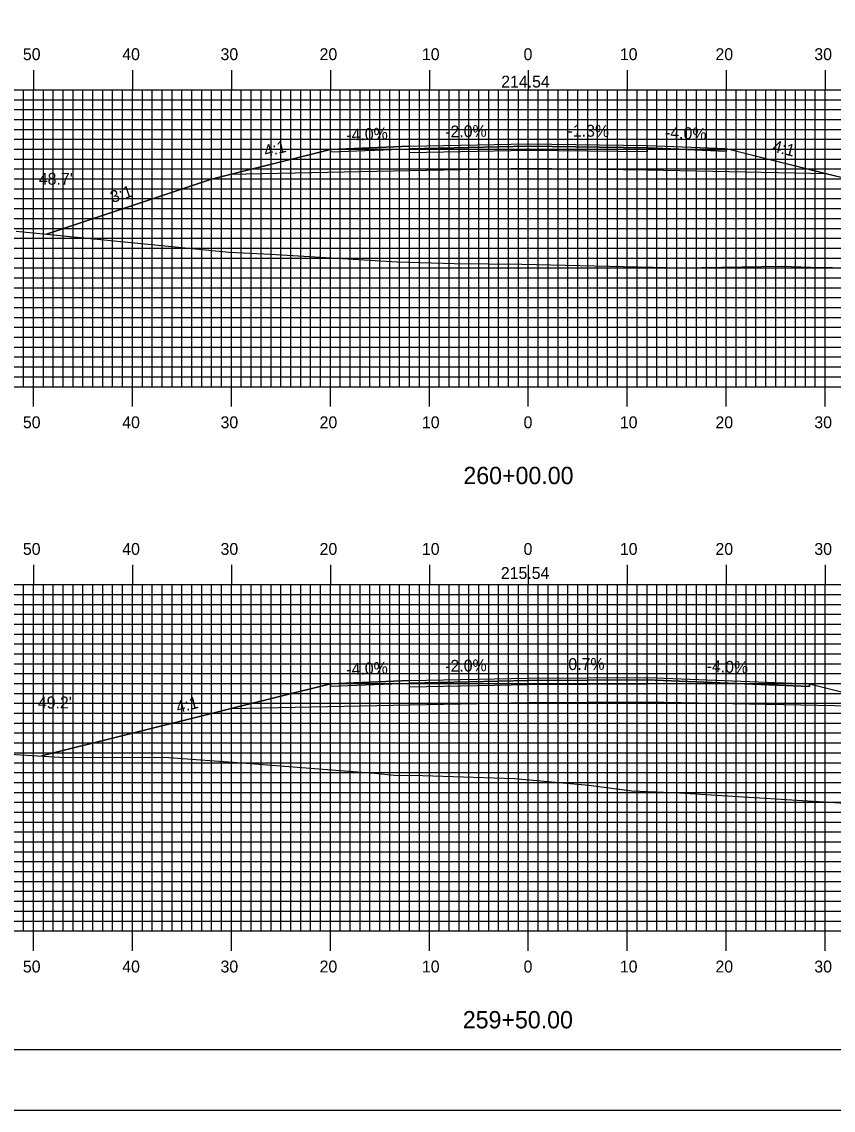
# Model space of a CAD drawing. Extents: x 1805864 to 1806208, y 442591 to 442811.
# Drawn here: x 1805979 to 1806061, y 442590.5 to 442700.5 of the extents above; entities that cross this region are included whole.
import ezdxf

# ---------------------------------------------------------------- set-up
doc = ezdxf.new("R2010")
doc.units = 0
for name, color, linetype in [('ANNOTATION', 7, 'Continuous'), ('BORDER', 7, 'Continuous'), ('D_Roadway_Centerline', 7, 'Continuous'), ('D_Roadway_Centerline_Text', 7, 'Continuous'), ('D_Roadway_Edge_Shoulder', 7, 'Continuous'), ('D_Roadway_Edge_TW', 7, 'Continuous'), ('D_Roadway_Pavement', 7, 'Continuous'), ('D_Roadway_SlopeLines', 7, 'Continuous'), ('D_Roadway_SubGrade', 7, 'Continuous'), ('D_Text_Standard', 7, 'Continuous'), ('H_V ANNOTATION', 7, 'Continuous'), ('MAJOR', 7, 'Continuous'), ('MINOR', 7, 'Continuous'), ('PLOT BOUNDARY', 7, 'Continuous'), ('S_Roadway_Centerline', 7, 'Continuous')]:
    doc.layers.add(name, color=color, linetype=linetype)

msp = doc.modelspace()

# ---------------------------------------------------------------- linework, layer by layer
at = {"layer": 'BORDER'}
msp.add_lwpolyline([(1805880.62, 442596.67), (1806200.62, 442596.67), (1806200.62, 442806.67), (1805880.62, 442806.67)], close=True, dxfattribs=at)
at = {"layer": 'D_Roadway_Centerline'}
for points in [[(1805981.53, 442679.08), (1805998.22, 442684.65), (1806000.05, 442685.1), (1806010.22, 442687.65), (1806018.22, 442687.97), (1806030.22, 442688.21), (1806042.22, 442688.05), (1806050.22, 442687.73), (1806060.39, 442685.19), (1806062.22, 442684.73), (1806093.95, 442674.16)], [(1805981.03, 442626.35), (1805998.22, 442630.65), (1806000.05, 442631.1), (1806010.22, 442633.65), (1806018.22, 442633.97), (1806030.22, 442634.21), (1806042.22, 442634.29), (1806058.63, 442633.63), (1806068.08, 442631.27), (1806070.63, 442630.63), (1806101.56, 442620.32)]]:
    msp.add_lwpolyline(points, dxfattribs=at)
at = {"layer": 'D_Roadway_Edge_Shoulder'}
for points in [[(1806018.22, 442687.97), (1806010.22, 442687.65), (1806010.22, 442687.4), (1806018.22, 442687.72)], [(1806042.22, 442688.05), (1806050.22, 442687.73), (1806050.22, 442687.48), (1806042.22, 442687.8)], [(1806018.22, 442633.97), (1806010.22, 442633.65), (1806010.22, 442633.4), (1806018.22, 442633.72)], [(1806042.22, 442634.29), (1806058.63, 442633.63), (1806058.63, 442633.38), (1806042.22, 442634.04)]]:
    msp.add_lwpolyline(points, close=True, dxfattribs=at)
at = {"layer": 'D_Roadway_Edge_TW'}
for points in [[(1806018.22, 442687.72), (1806018.22, 442687.97), (1806030.22, 442688.21), (1806042.22, 442688.05), (1806042.22, 442687.8), (1806030.22, 442687.96)], [(1806018.22, 442633.72), (1806018.22, 442633.97), (1806030.22, 442634.21), (1806042.22, 442634.29), (1806042.22, 442634.04), (1806030.22, 442633.96)]]:
    msp.add_lwpolyline(points, close=True, dxfattribs=at)
at = {"layer": 'D_Roadway_Pavement'}
for points in [[(1806018.22, 442687.3), (1806018.22, 442687.72), (1806030.22, 442687.96), (1806042.22, 442687.8), (1806042.22, 442687.39), (1806030.22, 442687.54)], [(1806018.22, 442633.3), (1806018.22, 442633.72), (1806030.22, 442633.96), (1806042.22, 442634.04), (1806042.22, 442633.62), (1806030.22, 442633.54)]]:
    msp.add_lwpolyline(points, close=True, dxfattribs=at)
at = {"layer": 'D_Roadway_SlopeLines'}
for points in [[(1806010.22, 442687.65), (1805998.22, 442684.65), (1805981.53, 442679.08)], [(1806050.22, 442687.73), (1806062.22, 442684.73), (1806093.95, 442674.16)], [(1806010.22, 442633.65), (1806000.05, 442631.1), (1805998.22, 442630.65), (1805981.03, 442626.35)], [(1806058.63, 442633.63), (1806070.63, 442630.63), (1806101.56, 442620.32)]]:
    msp.add_lwpolyline(points, dxfattribs=at)
at = {"layer": 'D_Roadway_SubGrade'}
for points in [[(1806018.22, 442685.47), (1806000.05, 442685.1), (1806010.22, 442687.65), (1806010.22, 442687.4), (1806018.22, 442687.72), (1806030.22, 442687.96), (1806042.22, 442687.8), (1806050.22, 442687.48), (1806050.22, 442687.73), (1806060.39, 442685.19), (1806042.22, 442685.55), (1806030.22, 442685.71)], [(1806018.22, 442631.47), (1806000.05, 442631.1), (1806010.22, 442633.65), (1806010.22, 442633.4), (1806018.22, 442633.72), (1806030.22, 442633.96), (1806042.22, 442634.04), (1806058.63, 442633.38), (1806058.63, 442633.63), (1806068.08, 442631.27), (1806042.22, 442631.79), (1806030.22, 442631.71)]]:
    msp.add_lwpolyline(points, close=True, dxfattribs=at)
at = {"layer": 'MAJOR'}
for p, q in [((1805980.22, 442695.67), (1805980.22, 442693.67)), ((1805990.22, 442695.67), (1805990.22, 442693.67)), ((1806000.22, 442695.67), (1806000.22, 442693.67)), ((1806010.22, 442695.67), (1806010.22, 442693.67)), ((1806020.22, 442695.67), (1806020.22, 442693.67)), ((1806030.22, 442695.67), (1806030.22, 442693.67)), ((1806040.22, 442695.67), (1806040.22, 442693.67)), ((1806050.22, 442695.67), (1806050.22, 442693.67)), ((1806060.22, 442695.67), (1806060.22, 442693.67)), ((1805890.22, 442693.67), (1806170.22, 442693.67)), ((1805890.22, 442693.67), (1806170.22, 442693.67)), ((1805980.22, 442663.67), (1805980.22, 442693.67)), ((1805990.22, 442663.67), (1805990.22, 442693.67)), ((1806000.22, 442663.67), (1806000.22, 442693.67)), ((1806010.22, 442663.67), (1806010.22, 442693.67)), ((1806020.22, 442663.67), (1806020.22, 442693.67)), ((1806030.22, 442663.67), (1806030.22, 442693.67)), ((1806040.22, 442663.67), (1806040.22, 442693.67)), ((1806050.22, 442663.67), (1806050.22, 442693.67)), ((1806060.22, 442663.67), (1806060.22, 442693.67)), ((1805890.22, 442688.67), (1806170.22, 442688.67)), ((1805890.22, 442683.67), (1806170.22, 442683.67)), ((1805890.22, 442678.67), (1806170.22, 442678.67)), ((1805890.22, 442673.67), (1806170.22, 442673.67)), ((1805890.22, 442668.67), (1806170.22, 442668.67)), ((1805890.22, 442663.67), (1806170.22, 442663.67)), ((1805890.22, 442663.67), (1806170.22, 442663.67)), ((1805980.22, 442661.66), (1805980.22, 442663.67)), ((1805990.22, 442661.66), (1805990.22, 442663.67)), ((1806000.22, 442661.66), (1806000.22, 442663.67)), ((1806010.22, 442661.66), (1806010.22, 442663.67)), ((1806020.22, 442661.66), (1806020.22, 442663.67)), ((1806030.22, 442661.66), (1806030.22, 442663.67)), ((1806040.22, 442661.66), (1806040.22, 442663.67)), ((1806050.22, 442661.66), (1806050.22, 442663.67)), ((1806060.22, 442661.66), (1806060.22, 442663.67)), ((1805980.22, 442645.67), (1805980.22, 442643.67)), ((1805990.22, 442645.67), (1805990.22, 442643.67)), ((1806000.22, 442645.67), (1806000.22, 442643.67)), ((1806010.22, 442645.67), (1806010.22, 442643.67)), ((1806020.22, 442645.67), (1806020.22, 442643.67)), ((1806030.22, 442645.67), (1806030.22, 442643.67)), ((1806040.22, 442645.67), (1806040.22, 442643.67)), ((1806050.22, 442645.67), (1806050.22, 442643.67)), ((1806060.22, 442645.67), (1806060.22, 442643.67)), ((1805890.22, 442643.67), (1806170.22, 442643.67)), ((1805890.22, 442643.67), (1806170.22, 442643.67)), ((1805980.22, 442608.67), (1805980.22, 442643.67)), ((1805990.22, 442608.67), (1805990.22, 442643.67)), ((1806000.22, 442608.67), (1806000.22, 442643.67)), ((1806010.22, 442608.67), (1806010.22, 442643.67)), ((1806020.22, 442608.67), (1806020.22, 442643.67)), ((1806030.22, 442608.67), (1806030.22, 442643.67)), ((1806040.22, 442608.67), (1806040.22, 442643.67)), ((1806050.22, 442608.67), (1806050.22, 442643.67)), ((1806060.22, 442608.67), (1806060.22, 442643.67)), ((1805890.22, 442638.67), (1806170.22, 442638.67)), ((1805890.22, 442633.67), (1806170.22, 442633.67)), ((1805890.22, 442628.67), (1806170.22, 442628.67)), ((1805890.22, 442623.67), (1806170.22, 442623.67)), ((1805890.22, 442618.67), (1806170.22, 442618.67)), ((1805890.22, 442613.67), (1806170.22, 442613.67)), ((1805890.22, 442608.67), (1806170.22, 442608.67)), ((1805890.22, 442608.67), (1806170.22, 442608.67)), ((1805980.22, 442606.66), (1805980.22, 442608.67)), ((1805990.22, 442606.66), (1805990.22, 442608.67)), ((1806000.22, 442606.66), (1806000.22, 442608.67)), ((1806010.22, 442606.66), (1806010.22, 442608.67)), ((1806020.22, 442606.66), (1806020.22, 442608.67)), ((1806030.22, 442606.66), (1806030.22, 442608.67)), ((1806040.22, 442606.66), (1806040.22, 442608.67)), ((1806050.22, 442606.66), (1806050.22, 442608.67)), ((1806060.22, 442606.66), (1806060.22, 442608.67))]:
    msp.add_line(p, q, dxfattribs=at)
at = {"layer": 'MINOR'}
for p, q in [((1805979.22, 442663.67), (1805979.22, 442693.67)), ((1805981.22, 442663.67), (1805981.22, 442693.67)), ((1805982.22, 442663.67), (1805982.22, 442693.67)), ((1805983.22, 442663.67), (1805983.22, 442693.67)), ((1805984.22, 442663.67), (1805984.22, 442693.67)), ((1805985.22, 442663.67), (1805985.22, 442693.67)), ((1805986.22, 442663.67), (1805986.22, 442693.67)), ((1805987.22, 442663.67), (1805987.22, 442693.67)), ((1805988.22, 442663.67), (1805988.22, 442693.67)), ((1805989.22, 442663.67), (1805989.22, 442693.67)), ((1805991.22, 442663.67), (1805991.22, 442693.67)), ((1805992.22, 442663.67), (1805992.22, 442693.67)), ((1805993.22, 442663.67), (1805993.22, 442693.67)), ((1805994.22, 442663.67), (1805994.22, 442693.67)), ((1805995.22, 442663.67), (1805995.22, 442693.67)), ((1805996.22, 442663.67), (1805996.22, 442693.67)), ((1805997.22, 442663.67), (1805997.22, 442693.67)), ((1805998.22, 442663.67), (1805998.22, 442693.67)), ((1805999.22, 442663.67), (1805999.22, 442693.67)), ((1806001.22, 442663.67), (1806001.22, 442693.67)), ((1806002.22, 442663.67), (1806002.22, 442693.67)), ((1806003.22, 442663.67), (1806003.22, 442693.67)), ((1806004.22, 442663.67), (1806004.22, 442693.67)), ((1806005.22, 442663.67), (1806005.22, 442693.67)), ((1806006.22, 442663.67), (1806006.22, 442693.67)), ((1806007.22, 442663.67), (1806007.22, 442693.67)), ((1806008.22, 442663.67), (1806008.22, 442693.67)), ((1806009.22, 442663.67), (1806009.22, 442693.67)), ((1806011.22, 442663.67), (1806011.22, 442693.67)), ((1806012.22, 442663.67), (1806012.22, 442693.67)), ((1806013.22, 442663.67), (1806013.22, 442693.67)), ((1806014.22, 442663.67), (1806014.22, 442693.67)), ((1806015.22, 442663.67), (1806015.22, 442693.67)), ((1806016.22, 442663.67), (1806016.22, 442693.67)), ((1806017.22, 442663.67), (1806017.22, 442693.67)), ((1806018.22, 442663.67), (1806018.22, 442693.67)), ((1806019.22, 442663.67), (1806019.22, 442693.67)), ((1806021.22, 442663.67), (1806021.22, 442693.67)), ((1806022.22, 442663.67), (1806022.22, 442693.67)), ((1806023.22, 442663.67), (1806023.22, 442693.67)), ((1806024.22, 442663.67), (1806024.22, 442693.67)), ((1806025.22, 442663.67), (1806025.22, 442693.67)), ((1806026.22, 442663.67), (1806026.22, 442693.67)), ((1806027.22, 442663.67), (1806027.22, 442693.67)), ((1806028.22, 442663.67), (1806028.22, 442693.67)), ((1806029.22, 442663.67), (1806029.22, 442693.67)), ((1806031.22, 442663.67), (1806031.22, 442693.67)), ((1806032.22, 442663.67), (1806032.22, 442693.67)), ((1806033.22, 442663.67), (1806033.22, 442693.67)), ((1806034.22, 442663.67), (1806034.22, 442693.67)), ((1806035.22, 442663.67), (1806035.22, 442693.67)), ((1806036.22, 442663.67), (1806036.22, 442693.67)), ((1806037.22, 442663.67), (1806037.22, 442693.67)), ((1806038.22, 442663.67), (1806038.22, 442693.67)), ((1806039.22, 442663.67), (1806039.22, 442693.67)), ((1806041.22, 442663.67), (1806041.22, 442693.67)), ((1806042.22, 442663.67), (1806042.22, 442693.67)), ((1806043.22, 442663.67), (1806043.22, 442693.67)), ((1806044.22, 442663.67), (1806044.22, 442693.67)), ((1806045.22, 442663.67), (1806045.22, 442693.67)), ((1806046.22, 442663.67), (1806046.22, 442693.67)), ((1806047.22, 442663.67), (1806047.22, 442693.67)), ((1806048.22, 442663.67), (1806048.22, 442693.67)), ((1806049.22, 442663.67), (1806049.22, 442693.67)), ((1806051.22, 442663.67), (1806051.22, 442693.67)), ((1806052.22, 442663.67), (1806052.22, 442693.67)), ((1806053.22, 442663.67), (1806053.22, 442693.67)), ((1806054.22, 442663.67), (1806054.22, 442693.67)), ((1806055.22, 442663.67), (1806055.22, 442693.67)), ((1806056.22, 442663.67), (1806056.22, 442693.67)), ((1806057.22, 442663.67), (1806057.22, 442693.67)), ((1806058.22, 442663.67), (1806058.22, 442693.67)), ((1806059.22, 442663.67), (1806059.22, 442693.67)), ((1805890.22, 442692.67), (1806170.22, 442692.67)), ((1805890.22, 442691.67), (1806170.22, 442691.67)), ((1805890.22, 442690.67), (1806170.22, 442690.67)), ((1805890.22, 442689.67), (1806170.22, 442689.67)), ((1805890.22, 442687.67), (1806170.22, 442687.67)), ((1805890.22, 442686.67), (1806170.22, 442686.67)), ((1805890.22, 442685.67), (1806170.22, 442685.67)), ((1805890.22, 442684.67), (1806170.22, 442684.67)), ((1805890.22, 442682.67), (1806170.22, 442682.67)), ((1805890.22, 442681.67), (1806170.22, 442681.67)), ((1805890.22, 442680.67), (1806170.22, 442680.67)), ((1805890.22, 442679.67), (1806170.22, 442679.67)), ((1805890.22, 442677.67), (1806170.22, 442677.67)), ((1805890.22, 442676.67), (1806170.22, 442676.67)), ((1805890.22, 442675.67), (1806170.22, 442675.67)), ((1805890.22, 442674.67), (1806170.22, 442674.67)), ((1805890.22, 442672.67), (1806170.22, 442672.67)), ((1805890.22, 442671.67), (1806170.22, 442671.67)), ((1805890.22, 442670.67), (1806170.22, 442670.67)), ((1805890.22, 442669.67), (1806170.22, 442669.67)), ((1805890.22, 442667.67), (1806170.22, 442667.67)), ((1805890.22, 442666.67), (1806170.22, 442666.67)), ((1805890.22, 442665.67), (1806170.22, 442665.67)), ((1805890.22, 442664.67), (1806170.22, 442664.67)), ((1805979.22, 442608.67), (1805979.22, 442643.67)), ((1805981.22, 442608.67), (1805981.22, 442643.67)), ((1805982.22, 442608.67), (1805982.22, 442643.67)), ((1805983.22, 442608.67), (1805983.22, 442643.67)), ((1805984.22, 442608.67), (1805984.22, 442643.67)), ((1805985.22, 442608.67), (1805985.22, 442643.67)), ((1805986.22, 442608.67), (1805986.22, 442643.67)), ((1805987.22, 442608.67), (1805987.22, 442643.67)), ((1805988.22, 442608.67), (1805988.22, 442643.67)), ((1805989.22, 442608.67), (1805989.22, 442643.67)), ((1805991.22, 442608.67), (1805991.22, 442643.67)), ((1805992.22, 442608.67), (1805992.22, 442643.67)), ((1805993.22, 442608.67), (1805993.22, 442643.67)), ((1805994.22, 442608.67), (1805994.22, 442643.67)), ((1805995.22, 442608.67), (1805995.22, 442643.67)), ((1805996.22, 442608.67), (1805996.22, 442643.67)), ((1805997.22, 442608.67), (1805997.22, 442643.67)), ((1805998.22, 442608.67), (1805998.22, 442643.67)), ((1805999.22, 442608.67), (1805999.22, 442643.67)), ((1806001.22, 442608.67), (1806001.22, 442643.67)), ((1806002.22, 442608.67), (1806002.22, 442643.67)), ((1806003.22, 442608.67), (1806003.22, 442643.67)), ((1806004.22, 442608.67), (1806004.22, 442643.67)), ((1806005.22, 442608.67), (1806005.22, 442643.67)), ((1806006.22, 442608.67), (1806006.22, 442643.67)), ((1806007.22, 442608.67), (1806007.22, 442643.67)), ((1806008.22, 442608.67), (1806008.22, 442643.67)), ((1806009.22, 442608.67), (1806009.22, 442643.67)), ((1806011.22, 442608.67), (1806011.22, 442643.67)), ((1806012.22, 442608.67), (1806012.22, 442643.67)), ((1806013.22, 442608.67), (1806013.22, 442643.67)), ((1806014.22, 442608.67), (1806014.22, 442643.67)), ((1806015.22, 442608.67), (1806015.22, 442643.67)), ((1806016.22, 442608.67), (1806016.22, 442643.67)), ((1806017.22, 442608.67), (1806017.22, 442643.67)), ((1806018.22, 442608.67), (1806018.22, 442643.67)), ((1806019.22, 442608.67), (1806019.22, 442643.67)), ((1806021.22, 442608.67), (1806021.22, 442643.67)), ((1806022.22, 442608.67), (1806022.22, 442643.67)), ((1806023.22, 442608.67), (1806023.22, 442643.67)), ((1806024.22, 442608.67), (1806024.22, 442643.67)), ((1806025.22, 442608.67), (1806025.22, 442643.67)), ((1806026.22, 442608.67), (1806026.22, 442643.67)), ((1806027.22, 442608.67), (1806027.22, 442643.67)), ((1806028.22, 442608.67), (1806028.22, 442643.67)), ((1806029.22, 442608.67), (1806029.22, 442643.67)), ((1806031.22, 442608.67), (1806031.22, 442643.67)), ((1806032.22, 442608.67), (1806032.22, 442643.67)), ((1806033.22, 442608.67), (1806033.22, 442643.67)), ((1806034.22, 442608.67), (1806034.22, 442643.67)), ((1806035.22, 442608.67), (1806035.22, 442643.67)), ((1806036.22, 442608.67), (1806036.22, 442643.67)), ((1806037.22, 442608.67), (1806037.22, 442643.67)), ((1806038.22, 442608.67), (1806038.22, 442643.67)), ((1806039.22, 442608.67), (1806039.22, 442643.67)), ((1806041.22, 442608.67), (1806041.22, 442643.67)), ((1806042.22, 442608.67), (1806042.22, 442643.67)), ((1806043.22, 442608.67), (1806043.22, 442643.67)), ((1806044.22, 442608.67), (1806044.22, 442643.67)), ((1806045.22, 442608.67), (1806045.22, 442643.67)), ((1806046.22, 442608.67), (1806046.22, 442643.67)), ((1806047.22, 442608.67), (1806047.22, 442643.67)), ((1806048.22, 442608.67), (1806048.22, 442643.67)), ((1806049.22, 442608.67), (1806049.22, 442643.67)), ((1806051.22, 442608.67), (1806051.22, 442643.67)), ((1806052.22, 442608.67), (1806052.22, 442643.67)), ((1806053.22, 442608.67), (1806053.22, 442643.67)), ((1806054.22, 442608.67), (1806054.22, 442643.67)), ((1806055.22, 442608.67), (1806055.22, 442643.67)), ((1806056.22, 442608.67), (1806056.22, 442643.67)), ((1806057.22, 442608.67), (1806057.22, 442643.67)), ((1806058.22, 442608.67), (1806058.22, 442643.67)), ((1806059.22, 442608.67), (1806059.22, 442643.67)), ((1805890.22, 442642.67), (1806170.22, 442642.67)), ((1805890.22, 442641.67), (1806170.22, 442641.67)), ((1805890.22, 442640.67), (1806170.22, 442640.67)), ((1805890.22, 442639.67), (1806170.22, 442639.67)), ((1805890.22, 442637.67), (1806170.22, 442637.67)), ((1805890.22, 442636.67), (1806170.22, 442636.67)), ((1805890.22, 442635.67), (1806170.22, 442635.67)), ((1805890.22, 442634.67), (1806170.22, 442634.67)), ((1805890.22, 442632.67), (1806170.22, 442632.67)), ((1805890.22, 442631.67), (1806170.22, 442631.67)), ((1805890.22, 442630.67), (1806170.22, 442630.67)), ((1805890.22, 442629.67), (1806170.22, 442629.67)), ((1805890.22, 442627.67), (1806170.22, 442627.67)), ((1805890.22, 442626.67), (1806170.22, 442626.67)), ((1805890.22, 442625.67), (1806170.22, 442625.67)), ((1805890.22, 442624.67), (1806170.22, 442624.67)), ((1805890.22, 442622.67), (1806170.22, 442622.67)), ((1805890.22, 442621.67), (1806170.22, 442621.67)), ((1805890.22, 442620.67), (1806170.22, 442620.67)), ((1805890.22, 442619.67), (1806170.22, 442619.67)), ((1805890.22, 442617.67), (1806170.22, 442617.67)), ((1805890.22, 442616.67), (1806170.22, 442616.67)), ((1805890.22, 442615.67), (1806170.22, 442615.67)), ((1805890.22, 442614.67), (1806170.22, 442614.67)), ((1805890.22, 442612.67), (1806170.22, 442612.67)), ((1805890.22, 442611.67), (1806170.22, 442611.67)), ((1805890.22, 442610.67), (1806170.22, 442610.67)), ((1805890.22, 442609.67), (1806170.22, 442609.67))]:
    msp.add_line(p, q, dxfattribs=at)
at = {"layer": 'PLOT BOUNDARY'}
msp.add_lwpolyline([(1805864.43, 442590.55), (1806204.43, 442590.55), (1806204.43, 442810.55), (1805864.43, 442810.55)], close=True, dxfattribs=at)
at = {"layer": 'S_Roadway_Centerline'}
for points in [[(1805978.48, 442679.38), (1805999.99, 442677.25), (1806004.2, 442677.05), (1806016.96, 442676.28), (1806022.76, 442676.11), (1806029.55, 442676.04), (1806045.73, 442675.68), (1806055.84, 442675.85), (1806058.78, 442675.76), (1806069.77, 442675.59), (1806079.73, 442675.22), (1806081.03, 442675.24), (1806082.49, 442675.09), (1806100.88, 442673.59), (1806103.55, 442673.53), (1806107.22, 442673.47), (1806120.27, 442673.26), (1806132.04, 442673.29), (1806136.93, 442673.2), (1806141.24, 442673.03), (1806145.01, 442672.98), (1806163.14, 442672.64), (1806166.03, 442672.6), (1806170.22, 442672.45)], [(1805968.82, 442627.07), (1805982.88, 442626.24), (1805993.89, 442626.2), (1806001.27, 442625.65), (1806014.68, 442624.61), (1806016.68, 442624.4), (1806019.54, 442624.36), (1806028.84, 442624.06), (1806036.34, 442623.39), (1806040.68, 442622.84), (1806045.49, 442622.63), (1806063.3, 442621.52), (1806072, 442621.34), (1806075.48, 442621.21), (1806078.38, 442621.11), (1806098.23, 442620.43), (1806098.57, 442620.41), (1806098.9, 442620.42), (1806105.34, 442620.19)]]:
    msp.add_lwpolyline(points, dxfattribs=at)

# ---------------------------------------------------------------- texts
at = {"layer": 'ANNOTATION'}
for s, rotation, p in [('-4.0%', 2.2906, (1806011.85, 442688.51)), ('-2.0%', 1.1458, (1806021.83, 442688.84)), ('-1.3%', 359.268, (1806034.18, 442688.96)), ('-4.0%', 357.7094, (1806044.01, 442688.78)), ('4:1', 14.0362, (1806003.67, 442686.87)), ('4:1', 345.9638, (1806054.81, 442687.45)), ('3:1', 18.4348, (1805988.21, 442682.22)), ('-4.0%', 2.2906, (1806011.85, 442634.51)), ('-2.0%', 1.1458, (1806021.83, 442634.84)), ('0.7%', 0.3914, (1806034.27, 442635.03)), ('-4.0%', 357.7094, (1806048.22, 442634.85)), ('4:1', 14.0362, (1805994.8, 442630.68))]:
    msp.add_text(s, height=1.2, rotation=rotation, dxfattribs=at).set_placement(p)
at = {"layer": 'D_Roadway_Centerline'}
for s, p in [('C', (1806030.21, 442688.21)), ('L', (1806030.22, 442688.2)), ('C', (1806030.21, 442634.21)), ('L', (1806030.22, 442634.2))]:
    msp.add_text(s, height=0.0146, dxfattribs=at).set_placement(p)
at = {"layer": 'D_Roadway_Centerline_Text'}
for s, p in [('214.54', (1806027.48, 442693.9)), ('215.54', (1806027.44, 442644.24))]:
    msp.add_text(s, height=1.2, dxfattribs=at).set_placement(p)
at = {"layer": 'D_Text_Standard'}
for s, p in [("48.7'", (1805980.76, 442684.08)), ("49.2'", (1805980.66, 442631.15))]:
    msp.add_text(s, height=1.2, dxfattribs=at).set_placement(p)
at = {"layer": 'H_V ANNOTATION'}
for s, height, p in [('50', 1.2, (1805979.15, 442696.67)), ('40', 1.2, (1805989.19, 442696.67)), ('30', 1.2, (1805999.12, 442696.67)), ('20', 1.2, (1806009.13, 442696.67)), ('10', 1.2, (1806019.47, 442696.67)), ('0', 1.2, (1806029.74, 442696.67)), ('10', 1.2, (1806039.47, 442696.67)), ('20', 1.2, (1806049.13, 442696.67)), ('30', 1.2, (1806059.12, 442696.67)), ('50', 1.2, (1805979.15, 442659.47)), ('40', 1.2, (1805989.19, 442659.47)), ('30', 1.2, (1805999.12, 442659.47)), ('20', 1.2, (1806009.13, 442659.47)), ('10', 1.2, (1806019.47, 442659.47)), ('0', 1.2, (1806029.74, 442659.47)), ('10', 1.2, (1806039.47, 442659.47)), ('20', 1.2, (1806049.13, 442659.47)), ('30', 1.2, (1806059.12, 442659.47)), ('260+00.00', 1.75, (1806023.66, 442653.82)), ('50', 1.2, (1805979.15, 442646.67)), ('40', 1.2, (1805989.19, 442646.67)), ('30', 1.2, (1805999.12, 442646.67)), ('20', 1.2, (1806009.13, 442646.67)), ('10', 1.2, (1806019.47, 442646.67)), ('0', 1.2, (1806029.74, 442646.67)), ('10', 1.2, (1806039.47, 442646.67)), ('20', 1.2, (1806049.13, 442646.67)), ('30', 1.2, (1806059.12, 442646.67)), ('50', 1.2, (1805979.15, 442604.47)), ('40', 1.2, (1805989.19, 442604.47)), ('30', 1.2, (1805999.12, 442604.47)), ('20', 1.2, (1806009.13, 442604.47)), ('10', 1.2, (1806019.47, 442604.47)), ('0', 1.2, (1806029.74, 442604.47)), ('10', 1.2, (1806039.47, 442604.47)), ('20', 1.2, (1806049.13, 442604.47)), ('30', 1.2, (1806059.12, 442604.47)), ('259+50.00', 1.75, (1806023.6, 442598.82))]:
    msp.add_text(s, height=height, dxfattribs=at).set_placement(p)

doc.saveas('drawing.dxf')
